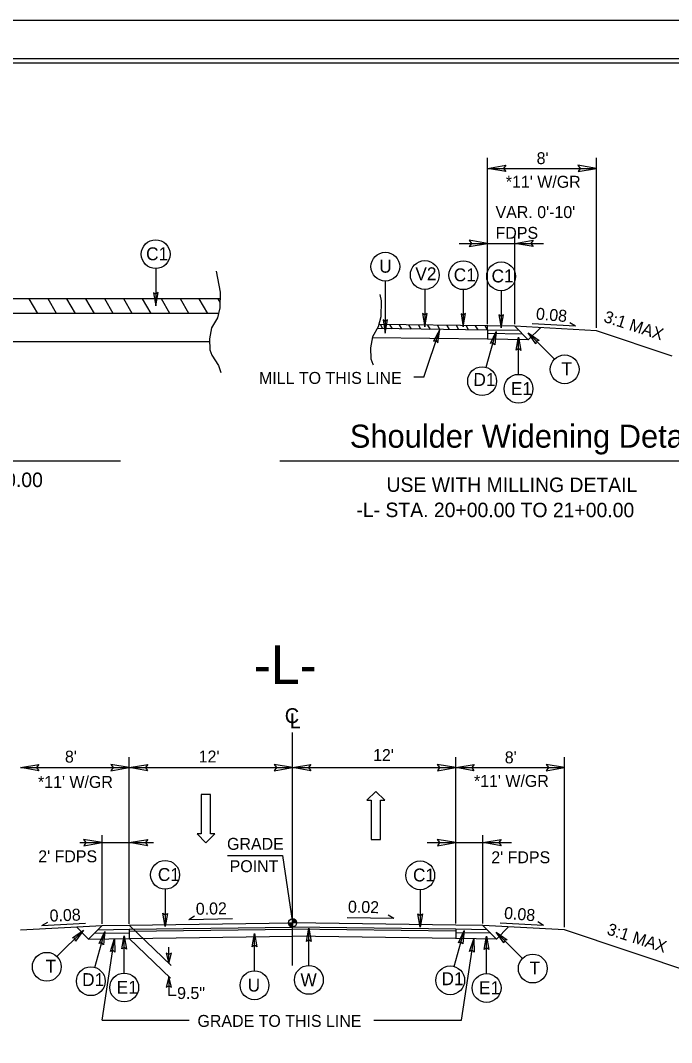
# Model space of a CAD drawing. Extents: x 1497225 to 1499181, y 579958 to 582278.
# Drawn here: x 1498169 to 1498551, y 581678 to 582278 of the extents above; entities that cross this region are included whole.
import ezdxf

# ---------------------------------------------------------------- set-up
doc = ezdxf.new("R2010")
doc.units = 0
for name, color, linetype in [('Old_Level_1', 7, 'Continuous'), ('Old_Level_11', 7, 'Continuous'), ('Old_Level_4', 7, 'Continuous'), ('Prop Dimension', 7, 'Continuous'), ('Prop Dimension Text', 7, 'Continuous'), ('Prop EOT', 7, 'Continuous'), ('Sheet Cutting Line CELL', 7, 'Continuous'), ('Sheet Plot Border Inside CELL', 7, 'Continuous'), ('Sheet Plot Border Outside CELL', 7, 'Continuous'), ('Sheet Typical CELL', 7, 'Continuous'), ('Typical Detail Wedge2 CELL', 7, 'Continuous'), ('Typical ID Circle CELL', 7, 'Continuous'), ('Typical Terminator CELL', 7, 'Continuous'), ('Typical Text General CELL', 7, 'Continuous'), ('Typical Text ID Circle CELL', 7, 'Continuous')]:
    doc.layers.add(name, color=color, linetype=linetype)

# ---------------------------------------------------------------- blocks, each defined once
blk = doc.blocks.new('TERMINATOR')
at = {"layer": 'Typical Terminator CELL'}
blk.add_lwpolyline([(-0.469, 0.081), (0, 0), (-0.471, -0.083), (-0.411, 0)], close=True, dxfattribs=at)

msp = doc.modelspace()

# ---------------------------------------------------------------- linework, layer by layer
at = {"layer": 'Old_Level_1'}
for p, q in [((1498442.61, 582099.7), (1498442.61, 582197.23)), ((1498506.46, 582097.48), (1498506.46, 582197.23)), ((1498442.61, 582191.09), (1498506.46, 582191.09)), ((1498425.92, 582147.08), (1498475.35, 582147.08)), ((1498458.57, 582134.06), (1498458.57, 582151.51)), ((1498458.57, 582099.7), (1498458.57, 582134.06)), ((1498442.77, 582098.68), (1498378.86, 582099.54)), ((1498442.77, 582098.68), (1498378.86, 582099.54)), ((1498458.57, 582098.47), (1498442.61, 582098.69)), ((1498442.61, 582096.2), (1498442.61, 582098.69)), ((1498506.46, 582095.81), (1498458.57, 582098.47)), ((1498458.57, 582098.47), (1498466.53, 582090.51)), ((1498468.69, 582100.07), (1498494.21, 582098.7)), ((1498490.83, 582100.74), (1498494.21, 582098.7)), ((1498442.61, 582096.2), (1498377.89, 582097.07)), ((1498405.26, 582068.58), (1498414.68, 582096.58)), ((1498461.09, 582095.95), (1498442.61, 582096.2)), ((1498442.61, 582096.2), (1498442.61, 582090.83)), ((1498463.18, 582093.85), (1498442.61, 582094.13)), ((1498466.53, 582090.51), (1498473.65, 582097.63)), ((1498550.92, 582080.99), (1498506.46, 582095.81)), ((1498442.61, 582090.83), (1498374.98, 582091.74)), ((1498466.53, 582090.51), (1498442.61, 582090.83)), ((1498405.26, 582068.58), (1498399.39, 582068.58)), ((1497951.27, 582019.56), (1498227.27, 582019.56)), ((1498320.75, 582019.56), (1498596.74, 582019.56)), ((1498328.14, 581723.32), (1498328.14, 581859.97)), ((1498232.38, 581747.77), (1498232.38, 581845.55)), ((1498423.91, 581748.02), (1498423.91, 581845.55)), ((1498487.76, 581745.8), (1498487.76, 581845.55)), ((1498168.53, 581839.41), (1498232.38, 581839.41)), ((1498232.38, 581839.41), (1498328.14, 581839.41)), ((1498328.14, 581839.41), (1498423.91, 581839.41)), ((1498423.91, 581839.41), (1498487.76, 581839.41)), ((1498216.42, 581779.42), (1498216.42, 581799.83)), ((1498439.87, 581782.38), (1498439.87, 581799.83)), ((1498203.47, 581795.4), (1498246.58, 581795.4)), ((1498407.22, 581795.4), (1498456.64, 581795.4)), ((1498290.05, 581787.8), (1498322.24, 581787.8)), ((1498322.24, 581787.8), (1498328.14, 581748.28)), ((1498439.87, 581748.02), (1498439.87, 581782.38)), ((1498216.42, 581747.77), (1498216.42, 581779.42)), ((1498267.33, 581750.37), (1498270.71, 581752.41)), ((1498267.33, 581750.37), (1498292.88, 581750.88)), ((1498328.14, 581748.28), (1498328.14, 581750.67)), ((1498387.69, 581750.79), (1498360.26, 581751.34)), ((1498387.69, 581750.79), (1498384.31, 581752.83)), ((1498168.53, 581744.13), (1498216.42, 581746.79)), ((1498181.16, 581746.68), (1498184.53, 581748.72)), ((1498181.16, 581746.68), (1498206.67, 581748.05)), ((1498201.33, 581745.95), (1498208.45, 581738.83)), ((1498208.45, 581738.83), (1498216.42, 581746.79)), ((1498213.9, 581744.27), (1498232.38, 581744.52)), ((1498216.42, 581746.79), (1498232.38, 581747.01)), ((1498232.38, 581747.01), (1498328.14, 581748.28)), ((1498256.87, 581723.23), (1498232.38, 581747.01)), ((1498232.38, 581744.52), (1498328.14, 581745.8)), ((1498232.38, 581744.52), (1498232.38, 581739.15)), ((1498232.41, 581743.41), (1498328.18, 581744.69)), ((1498325.76, 581748.28), (1498328.14, 581748.28)), ((1498423.87, 581743.41), (1498328.11, 581744.69)), ((1498423.91, 581747.01), (1498328.14, 581748.28)), ((1498330.53, 581748.28), (1498328.14, 581748.28)), ((1498328.14, 581745.9), (1498328.14, 581748.28)), ((1498328.14, 581748.28), (1498328.14, 581745.9)), ((1498423.91, 581744.52), (1498328.14, 581745.8)), ((1498439.87, 581746.79), (1498423.91, 581747.01)), ((1498442.38, 581744.27), (1498423.91, 581744.52)), ((1498423.91, 581744.52), (1498423.91, 581739.15)), ((1498487.76, 581744.13), (1498439.87, 581746.79)), ((1498439.87, 581746.79), (1498447.83, 581738.83)), ((1498447.83, 581738.83), (1498454.95, 581745.95)), ((1498449.98, 581748.39), (1498475.5, 581747.02)), ((1498472.13, 581749.06), (1498475.5, 581747.02)), ((1498208.45, 581738.83), (1498232.38, 581739.15)), ((1498211.8, 581742.17), (1498232.38, 581742.45)), ((1498216.57, 581691.19), (1498223.81, 581739.04)), ((1498256.63, 581715.77), (1498232.38, 581739.15)), ((1498232.54, 581739.16), (1498328.3, 581740.43)), ((1498423.74, 581739.16), (1498327.98, 581740.43)), ((1498444.48, 581742.17), (1498423.91, 581742.45)), ((1498447.83, 581738.83), (1498423.91, 581739.15)), ((1498427.28, 581691.19), (1498434.52, 581739.01)), ((1498568.54, 581717.2), (1498487.76, 581744.13)), ((1498255.65, 581724.41), (1498255.65, 581734.04)), ((1498255.65, 581716.71), (1498255.65, 581705.64)), ((1498259.97, 581705.67), (1498255.65, 581705.64)), ((1498216.57, 581691.19), (1498267.59, 581691.19)), ((1498375.9, 581691.19), (1498427.28, 581691.19))]:
    msp.add_line(p, q, dxfattribs=at)
for points in [[(1498328.16, 581750.67), (1498328.16, 581750.67), (1498328.16, 581748.28)], [(1498328.21, 581750.67), (1498328.21, 581748.28)], [(1498328.26, 581750.66), (1498328.26, 581748.28)], [(1498328.31, 581750.66), (1498328.31, 581748.28)], [(1498328.36, 581750.65), (1498328.36, 581748.28)], [(1498328.4, 581750.65), (1498328.4, 581748.28)], [(1498328.45, 581750.64), (1498328.45, 581748.28)], [(1498328.5, 581750.64), (1498328.5, 581748.28)], [(1498328.55, 581750.63), (1498328.55, 581748.28)], [(1498328.59, 581750.62), (1498328.59, 581748.28)], [(1498328.64, 581750.61), (1498328.64, 581748.28)], [(1498328.69, 581750.6), (1498328.69, 581748.28)], [(1498328.74, 581750.59), (1498328.74, 581748.28)], [(1498328.78, 581750.58), (1498328.78, 581748.28)], [(1498328.83, 581750.56), (1498328.83, 581748.28)], [(1498328.88, 581750.55), (1498328.88, 581748.28)], [(1498328.93, 581750.53), (1498328.93, 581748.28)], [(1498328.97, 581750.52), (1498328.97, 581748.28)], [(1498329.02, 581750.5), (1498329.02, 581748.28)], [(1498329.07, 581750.47), (1498329.07, 581748.28)], [(1498329.12, 581750.45), (1498329.12, 581748.28)], [(1498329.17, 581750.43), (1498329.17, 581748.28)], [(1498329.21, 581750.41), (1498329.21, 581748.28)], [(1498329.26, 581750.38), (1498329.26, 581748.28)], [(1498329.31, 581750.36), (1498329.31, 581748.28)], [(1498325.77, 581748.28), (1498325.77, 581748.02)], [(1498325.82, 581748.28), (1498325.82, 581747.74)], [(1498325.87, 581748.28), (1498325.87, 581747.57)], [(1498325.91, 581748.28), (1498325.91, 581747.43)], [(1498325.96, 581748.28), (1498325.96, 581747.32)], [(1498326.01, 581748.28), (1498326.01, 581747.22)], [(1498326.06, 581748.28), (1498326.06, 581747.13)], [(1498326.1, 581748.28), (1498326.1, 581747.04)], [(1498326.15, 581748.28), (1498326.15, 581746.97)], [(1498326.2, 581748.28), (1498326.2, 581746.9)], [(1498326.25, 581748.28), (1498326.25, 581746.84)], [(1498326.3, 581748.28), (1498326.3, 581746.78)], [(1498326.34, 581748.28), (1498326.34, 581746.72)], [(1498326.39, 581748.28), (1498326.39, 581746.67)], [(1498326.44, 581748.28), (1498326.44, 581746.62)], [(1498326.49, 581748.28), (1498326.49, 581746.57)], [(1498326.53, 581748.28), (1498326.53, 581746.53)], [(1498326.58, 581748.28), (1498326.58, 581746.48)], [(1498326.63, 581748.28), (1498326.63, 581746.44)], [(1498326.68, 581748.28), (1498326.68, 581746.4)], [(1498326.72, 581748.28), (1498326.72, 581746.37)], [(1498326.77, 581748.28), (1498326.77, 581746.34)], [(1498326.82, 581748.28), (1498326.82, 581746.3)], [(1498326.87, 581748.28), (1498326.87, 581746.27)], [(1498326.91, 581748.28), (1498326.91, 581746.24)], [(1498326.96, 581748.28), (1498326.96, 581746.21)], [(1498327.01, 581748.28), (1498327.01, 581746.19)], [(1498327.06, 581748.28), (1498327.06, 581746.16)], [(1498327.11, 581748.28), (1498327.11, 581746.14)], [(1498327.15, 581748.28), (1498327.15, 581746.12)], [(1498327.2, 581748.28), (1498327.2, 581746.1)], [(1498327.25, 581748.28), (1498327.25, 581746.08)], [(1498327.3, 581748.28), (1498327.3, 581746.05)], [(1498327.34, 581748.28), (1498327.34, 581746.04)], [(1498327.39, 581748.28), (1498327.39, 581746.02)], [(1498327.44, 581748.28), (1498327.44, 581746.01)], [(1498327.49, 581748.28), (1498327.49, 581746)], [(1498327.53, 581748.28), (1498327.53, 581745.98)], [(1498327.58, 581748.28), (1498327.58, 581745.97)], [(1498327.63, 581748.28), (1498327.63, 581745.96)], [(1498327.68, 581748.28), (1498327.68, 581745.95)], [(1498327.72, 581748.28), (1498327.72, 581745.94)], [(1498327.77, 581748.28), (1498327.77, 581745.93)], [(1498327.82, 581748.28), (1498327.82, 581745.92)], [(1498327.87, 581748.28), (1498327.87, 581745.92)], [(1498327.92, 581748.28), (1498327.92, 581745.91)], [(1498327.96, 581748.28), (1498327.96, 581745.91)], [(1498328.01, 581748.28), (1498328.01, 581745.91)], [(1498328.06, 581748.28), (1498328.06, 581745.9)], [(1498328.11, 581748.28), (1498328.11, 581745.9), (1498328.11, 581745.9)], [(1498329.36, 581750.33), (1498329.36, 581748.28)], [(1498329.4, 581750.31), (1498329.4, 581748.28)], [(1498329.45, 581750.27), (1498329.45, 581748.28)], [(1498329.5, 581750.24), (1498329.5, 581748.28)], [(1498329.55, 581750.2), (1498329.55, 581748.28)], [(1498329.59, 581750.17), (1498329.59, 581748.28)], [(1498329.64, 581750.14), (1498329.64, 581748.28)], [(1498329.69, 581750.09), (1498329.69, 581748.28)], [(1498329.74, 581750.05), (1498329.74, 581748.28)], [(1498329.79, 581750.01), (1498329.79, 581748.28)], [(1498329.83, 581749.96), (1498329.83, 581748.28)], [(1498329.88, 581749.91), (1498329.88, 581748.28)], [(1498329.93, 581749.86), (1498329.93, 581748.28)], [(1498329.98, 581749.8), (1498329.98, 581748.28)], [(1498330.02, 581749.74), (1498330.02, 581748.28)], [(1498330.07, 581749.68), (1498330.07, 581748.28)], [(1498330.12, 581749.61), (1498330.12, 581748.28)], [(1498330.17, 581749.54), (1498330.17, 581748.28)], [(1498330.21, 581749.46), (1498330.21, 581748.28)], [(1498330.26, 581749.37), (1498330.26, 581748.28)], [(1498330.31, 581749.27), (1498330.31, 581748.28)], [(1498330.36, 581749.16), (1498330.36, 581748.28)], [(1498330.4, 581749.03), (1498330.4, 581748.28)], [(1498330.45, 581748.87), (1498330.45, 581748.28)], [(1498330.5, 581748.62), (1498330.5, 581748.28)]]:
    msp.add_lwpolyline(points, dxfattribs=at)
msp.add_ellipse((1498328.14, 581748.28), major_axis=(2.38, 0), ratio=0.9995, dxfattribs=at)
for major_axis in [(2.38, 0), (-2.38, 0)]:
    msp.add_ellipse((1498328.14, 581748.28), major_axis=major_axis, ratio=0.9995, start_param=6.283019, end_param=7.853815, dxfattribs=at)
at = {"layer": 'Old_Level_11'}
for points in [[(1498453.33, 582189.2), (1498442.61, 582191.09), (1498453.42, 582192.98), (1498452.05, 582191.09)], [(1498495.73, 582189.2), (1498506.46, 582191.09), (1498495.65, 582192.98), (1498497.02, 582191.09)], [(1498431.88, 582145.19), (1498442.61, 582147.08), (1498431.8, 582148.97), (1498433.17, 582147.08)], [(1498469.3, 582145.19), (1498458.57, 582147.08), (1498469.38, 582148.97), (1498468.01, 582147.08)], [(1498179.26, 581837.52), (1498168.53, 581839.41), (1498179.34, 581841.3), (1498177.97, 581839.41)], [(1498221.66, 581837.52), (1498232.38, 581839.41), (1498221.57, 581841.3), (1498222.94, 581839.41)], [(1498243.11, 581837.52), (1498232.38, 581839.41), (1498243.19, 581841.3), (1498241.82, 581839.41)], [(1498317.42, 581837.52), (1498328.14, 581839.41), (1498317.33, 581841.3), (1498318.71, 581839.41)], [(1498338.87, 581837.52), (1498328.14, 581839.41), (1498338.95, 581841.3), (1498337.58, 581839.41)], [(1498413.18, 581837.52), (1498423.91, 581839.41), (1498413.1, 581841.3), (1498414.47, 581839.41)], [(1498434.63, 581837.52), (1498423.91, 581839.41), (1498434.72, 581841.3), (1498433.34, 581839.41)], [(1498477.03, 581837.52), (1498487.76, 581839.41), (1498476.95, 581841.3), (1498478.32, 581839.41)], [(1498205.69, 581793.51), (1498216.42, 581795.4), (1498205.61, 581797.29), (1498206.98, 581795.4)], [(1498243.11, 581793.51), (1498232.38, 581795.4), (1498243.19, 581797.29), (1498241.82, 581795.4)], [(1498413.18, 581793.51), (1498423.91, 581795.4), (1498413.1, 581797.29), (1498414.47, 581795.4)], [(1498450.59, 581793.51), (1498439.87, 581795.4), (1498450.68, 581797.29), (1498449.3, 581795.4)]]:
    msp.add_lwpolyline(points, close=True, dxfattribs=at)
at = {"layer": 'Old_Level_4'}
for p, q in [((1498274.65, 581823.65), (1498274.65, 581800.55)), ((1498280.1, 581823.65), (1498274.65, 581823.65)), ((1498280.1, 581800.55), (1498280.1, 581823.65)), ((1498377.15, 581825.46), (1498371.87, 581820.26)), ((1498382.26, 581820.26), (1498377.15, 581825.46)), ((1498371.87, 581820.26), (1498374.34, 581820.26)), ((1498374.34, 581820.26), (1498374.34, 581797.16)), ((1498379.79, 581797.16), (1498379.79, 581820.26)), ((1498379.79, 581820.26), (1498382.26, 581820.26)), ((1498274.65, 581800.55), (1498272.18, 581800.55)), ((1498272.18, 581800.55), (1498277.29, 581795.35)), ((1498277.29, 581795.35), (1498282.57, 581800.55)), ((1498282.57, 581800.55), (1498280.1, 581800.55)), ((1498374.34, 581797.16), (1498379.79, 581797.16))]:
    msp.add_line(p, q, dxfattribs=at)
at = {"layer": 'Prop Dimension'}
msp.add_lwpolyline([(1498285.68, 582114.53), (1497932.02, 582114.53), (1497932.02, 582089.48), (1498279.23, 582089.48)], dxfattribs=at)
at = {"layer": 'Prop EOT'}
for p, q in [((1498285.68, 582114.53), (1498007.12, 582114.53)), ((1498178.64, 582105.93), (1498173.67, 582114.53)), ((1498189.72, 582105.93), (1498184.76, 582114.53)), ((1498200.81, 582105.93), (1498195.84, 582114.53)), ((1498211.89, 582105.93), (1498206.93, 582114.53)), ((1498222.98, 582105.93), (1498218.02, 582114.53)), ((1498234.06, 582105.93), (1498229.1, 582114.53)), ((1498245.15, 582105.93), (1498240.19, 582114.53)), ((1498256.24, 582105.93), (1498251.27, 582114.53)), ((1498267.32, 582105.93), (1498262.36, 582114.53)), ((1498278.41, 582105.93), (1498273.44, 582114.53)), ((1498285.64, 582112.59), (1498284.53, 582114.53)), ((1498284.72, 582105.93), (1498007.12, 582105.93)), ((1498381.17, 582097.02), (1498379.72, 582099.52)), ((1498386.75, 582096.95), (1498385.31, 582099.45)), ((1498392.34, 582096.87), (1498390.9, 582099.38)), ((1498397.92, 582096.8), (1498396.48, 582099.3)), ((1498403.51, 582096.73), (1498402.07, 582099.23)), ((1498409.1, 582096.65), (1498407.65, 582099.15)), ((1498414.68, 582096.58), (1498413.24, 582099.08)), ((1498420.27, 582096.5), (1498418.82, 582099)), ((1498425.85, 582096.43), (1498424.41, 582098.93)), ((1498431.44, 582096.35), (1498429.99, 582098.85)), ((1498437.02, 582096.28), (1498435.58, 582098.78)), ((1498442.61, 582096.2), (1498441.17, 582098.71))]:
    msp.add_line(p, q, dxfattribs=at)
at = {"layer": 'Sheet Cutting Line CELL'}
msp.add_line((1498909.23, 582277.96), (1497225.23, 582277.96), dxfattribs=at)
at = {"layer": 'Sheet Plot Border Inside CELL'}
msp.add_lwpolyline([(1498904.73, 582255.51), (1497238.23, 582255.51), (1497238.23, 581200.41), (1498904.73, 581200.41)], close=True, dxfattribs=at)
at = {"layer": 'Sheet Plot Border Outside CELL'}
msp.add_lwpolyline([(1498909.23, 582277.96), (1497225.23, 582277.96), (1497225.23, 581177.96), (1498909.23, 581177.96)], close=True, dxfattribs=at)
at = {"layer": 'Sheet Typical CELL'}
msp.add_lwpolyline([(1498892.23, 582252.96), (1497392.23, 582252.96), (1497392.23, 581202.96), (1498892.23, 581202.96)], close=True, dxfattribs=at)
at = {"layer": 'Typical Detail Wedge2 CELL'}
for points in [[(1498283.32, 582130.8), (1498285.77, 582118.57), (1498285.58, 582109.25), (1498284.06, 582103.36), (1498280.63, 582097.46), (1498279.49, 582091), (1498279.68, 582084.54), (1498280.83, 582081.49), (1498284.81, 582075.41), (1498286.14, 582071.23)], [(1498379.43, 582117.13), (1498380.2, 582113.3), (1498380.01, 582103.98), (1498378.49, 582098.09), (1498375.06, 582092.19), (1498373.92, 582085.73), (1498374.11, 582079.27), (1498375.26, 582076.22), (1498375.54, 582075.79)]]:
    msp.add_lwpolyline(points, dxfattribs=at)
at = {"layer": 'Typical ID Circle CELL'}
for p, q in [((1498247.88, 582132.32), (1498247.88, 582110.45)), ((1498382.62, 582125), (1498382.62, 582094.43)), ((1498405.78, 582120.06), (1498405.78, 582098.19)), ((1498428.39, 582119.96), (1498428.39, 582098.09)), ((1498450.57, 582119.32), (1498450.57, 582097.45)), ((1498441.7, 582074.39), (1498447.65, 582095.44)), ((1498481.85, 582079.15), (1498466.38, 582094.61)), ((1498460.75, 582070.23), (1498460.75, 582092.1)), ((1498253.39, 581768.01), (1498253.39, 581746.14)), ((1498403.11, 581767.73), (1498403.11, 581745.86)), ((1498337.79, 581723.28), (1498337.79, 581745.15)), ((1498189.96, 581728.52), (1498205.43, 581743.99)), ((1498212.11, 581722.19), (1498218.06, 581743.24)), ((1498229.42, 581718.85), (1498229.42, 581740.72)), ((1498305.85, 581720.13), (1498305.85, 581742)), ((1498423, 581722.71), (1498428.94, 581743.76)), ((1498442.04, 581718.55), (1498442.04, 581740.42)), ((1498463.15, 581727.47), (1498447.68, 581742.93))]:
    msp.add_line(p, q, dxfattribs=at)
for centre in [(1498247.88, 582140.78), (1498382.62, 582133.46), (1498405.78, 582128.52), (1498428.39, 582128.42), (1498450.57, 582127.79), (1498487.83, 582073.16), (1498439.4, 582066.25), (1498460.75, 582061.77), (1498253.39, 581776.47), (1498403.11, 581776.19), (1498183.98, 581722.54), (1498469.13, 581721.48), (1498209.81, 581714.05), (1498337.79, 581714.82), (1498420.7, 581714.57), (1498229.42, 581710.39), (1498305.85, 581711.67), (1498442.04, 581710.09)]:
    msp.add_circle(centre, 8.46, dxfattribs=at)
at = {"layer": 'Typical Terminator CELL'}
for points in [[(1498246.55, 582118.18), (1498247.88, 582110.45), (1498249.25, 582118.23), (1498247.88, 582117.24)], [(1498404.45, 582105.93), (1498405.78, 582098.19), (1498407.16, 582105.97), (1498405.78, 582104.98)], [(1498427.05, 582105.82), (1498428.39, 582098.09), (1498429.76, 582105.87), (1498428.39, 582104.88)], [(1498449.24, 582105.19), (1498450.57, 582097.45), (1498451.95, 582105.23), (1498450.57, 582104.24)], [(1498381.28, 582102.17), (1498382.62, 582094.43), (1498383.99, 582102.21), (1498382.62, 582101.22)], [(1498413.48, 582088.82), (1498414.68, 582096.58), (1498410.9, 582089.64), (1498412.52, 582090.14)], [(1498444.26, 582088.36), (1498447.65, 582095.44), (1498446.86, 582087.58), (1498445.8, 582088.9)], [(1498470.91, 582088.2), (1498466.38, 582094.61), (1498472.85, 582090.09), (1498471.18, 582089.81)], [(1498459.41, 582084.37), (1498460.75, 582092.1), (1498462.12, 582084.33), (1498460.75, 582085.32)], [(1498254.72, 581753.87), (1498253.39, 581746.14), (1498252.01, 581753.91), (1498253.39, 581752.93)], [(1498404.44, 581753.59), (1498403.11, 581745.86), (1498401.73, 581753.63), (1498403.11, 581752.64)], [(1498336.46, 581737.42), (1498337.79, 581745.15), (1498339.17, 581737.37), (1498337.79, 581738.36)], [(1498199.02, 581739.46), (1498205.43, 581743.99), (1498200.9, 581737.52), (1498200.63, 581739.19)], [(1498214.68, 581736.16), (1498218.06, 581743.24), (1498217.27, 581735.39), (1498216.21, 581736.71)], [(1498221.33, 581731.59), (1498223.81, 581739.04), (1498224, 581731.14), (1498222.79, 581732.33)], [(1498228.09, 581732.99), (1498229.42, 581740.72), (1498230.8, 581732.95), (1498229.42, 581733.93)], [(1498304.52, 581734.27), (1498305.85, 581742), (1498307.22, 581734.23), (1498305.85, 581735.21)], [(1498425.56, 581736.68), (1498428.94, 581743.76), (1498428.15, 581735.9), (1498427.1, 581737.22)], [(1498432.03, 581731.56), (1498434.52, 581739.01), (1498434.7, 581731.11), (1498433.49, 581732.3)], [(1498440.71, 581732.69), (1498442.04, 581740.42), (1498443.42, 581732.65), (1498442.04, 581733.64)], [(1498452.21, 581736.52), (1498447.68, 581742.93), (1498454.15, 581738.41), (1498452.48, 581738.13)]]:
    msp.add_lwpolyline(points, close=True, dxfattribs=at)

# ---------------------------------------------------------------- block references
at = {"layer": 'Old_Level_4', "xscale": 13.123011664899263, "yscale": -18.835616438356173}
for p, rotation in [((1498255.65, 581724.41), -89.99999999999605), ((1498255.65, 581716.71), 90.00000000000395)]:
    msp.add_blockref('TERMINATOR', p, dxfattribs=dict(at, rotation=rotation))

# ---------------------------------------------------------------- texts
at = {"layer": 'Old_Level_1'}
for s, height, p in [("8'", 7, (1498471.41, 582193.61)), ("*11' W/GR", 7, (1498453.34, 582179.76)), ("VAR. 0'-10'", 7, (1498447.3, 582161.97)), ('FDPS', 7, (1498447.3, 582149.78)), ('MILL TO THIS LINE', 7, (1498308.49, 582064.64)), ('C', 8.73, (1498323.63, 581865.54)), ("8'", 7, (1498194.64, 581842.37)), ("12'", 7, (1498273.13, 581842.43)), ("12'", 7, (1498375.44, 581843.28)), ("8'", 7, (1498452.71, 581841.93)), ("*11' W/GR", 7, (1498178.84, 581827.51)), ("*11' W/GR", 7, (1498434.64, 581828.08)), ("2' FDPS", 7, (1498178.97, 581783.85)), ("2' FDPS", 7, (1498444.81, 581783.3)), ('GRADE TO THIS LINE', 7, (1498272.4, 581687.25))]:
    msp.add_text(s, height=height, dxfattribs=at).set_placement(p)
for s, height, rotation, p in [('0.08', 7, 355.23853, (1498470.8, 582102.44)), ('3:1 MAX', 7, 342.11243, (1498510.28, 582101.15)), ('-L- STA. 20+00.00 TO -L- STA. 21+00.00', 8.5, 359.94924, (1497973.18, 582004.26)), ('USE WITH MILLING DETAIL', 8.5, 359.94924, (1498383.32, 582001.26)), ('-L- STA. 20+00.00 TO 21+00.00', 8.5, 359.94924, (1498365.65, 581986.48)), ('-L-', 22.68, 359.94924, (1498305.33, 581888.46)), ('L', 8.73, 359.9469, (1498326.53, 581862.56)), ('0.08', 7, 2.06858, (1498185.77, 581749.02)), ('0.02', 7, 1.14574, (1498271.49, 581753.04)), ('0.02', 7, 358.85426, (1498360.66, 581754.33)), ('0.08', 7, 355.23853, (1498452.1, 581750.76)), ('3:1 MAX', 7, 342.11243, (1498512.13, 581741.69))]:
    msp.add_text(s, height=height, rotation=rotation, dxfattribs=at).set_placement(p)
at = {"layer": 'Old_Level_4'}
msp.add_text('9.5"', height=7, rotation=360, dxfattribs=at).set_placement((1498260.47, 581703.61))
at = {"layer": 'Prop Dimension Text'}
for s, p in [('GRADE', (1498289.75, 581791.18)), ('POINT', (1498291.28, 581778.06))]:
    msp.add_text(s, height=7, rotation=0.00014, dxfattribs=at).set_placement(p)
at = {"layer": 'Typical Text General CELL'}
msp.add_text('Shoulder Widening Detail', height=13.52, dxfattribs=at).set_placement((1498361.8, 582027.19))
at = {"layer": 'Typical Text ID Circle CELL'}
for s, height, p in [('C1', 7.575, (1498242.25, 582137.21)), ('U', 7.58, (1498379.06, 582129.89)), ('V2', 7.575, (1498400.25, 582125.49)), ('C1', 7.575, (1498422.76, 582124.85)), ('C1', 7.575, (1498444.95, 582124.21)), ('T', 7.58, (1498485.96, 582069.68)), ('E1', 7.575, (1498456.31, 582058.08)), ('C1', 7.575, (1498249.14, 581772.89)), ('C1', 7.575, (1498398.86, 581772.61)), ('T', 7.58, (1498183.32, 581719.05)), ('T', 7.58, (1498467.26, 581718)), ('U', 7.58, (1498301.86, 581707.98)), ('W', 7.58, (1498332.84, 581711.12)), ('E1', 7.575, (1498224.99, 581706.7)), ('E1', 7.575, (1498437.61, 581706.4))]:
    msp.add_text(s, height=height, dxfattribs=at).set_placement(p)
for p in [(1498434.31, 582063.41), (1498204.72, 581711.22), (1498415.6, 581711.73)]:
    msp.add_text('D1', height=7.575, rotation=359.94666, dxfattribs=at).set_placement(p)

doc.saveas('drawing.dxf')
